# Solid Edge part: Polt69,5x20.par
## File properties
Author: Türk
Template: Iso Part.par
Last saved by: Türk
Revision: 9
Application: Solid Edge
Accuracy: 0,990
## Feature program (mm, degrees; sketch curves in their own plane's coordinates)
thread "unnamed Thread 1"
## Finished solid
Body 1: solid body, 23 faces, 45 edges, 24 vertices.
  Faces by surface: plane 21, cylinder 2
  Edges by curve: line 42, circle 3
Bounding box of the edges (mm): 24.000 x 79.500 x 27.713, from (-12, -10, -13.8564) to (12, 69.5, 13.8564).
Cylindrical faces by radius (mm): R10 x2
Planar faces by outward normal: +x 1, +y 2, -x 1, -y 1, oblique 16
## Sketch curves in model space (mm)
circle centre (0, 0, 0) radius 13.8564
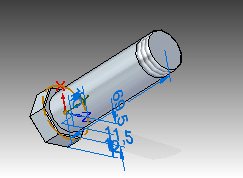
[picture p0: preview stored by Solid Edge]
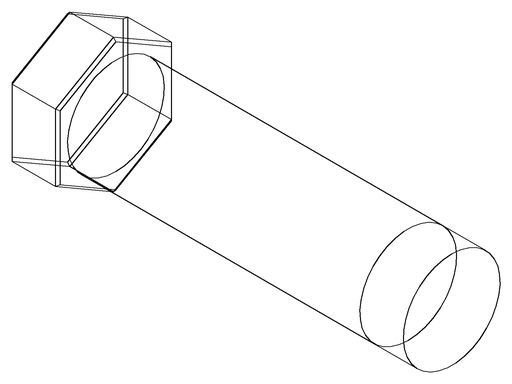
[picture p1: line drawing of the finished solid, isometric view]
